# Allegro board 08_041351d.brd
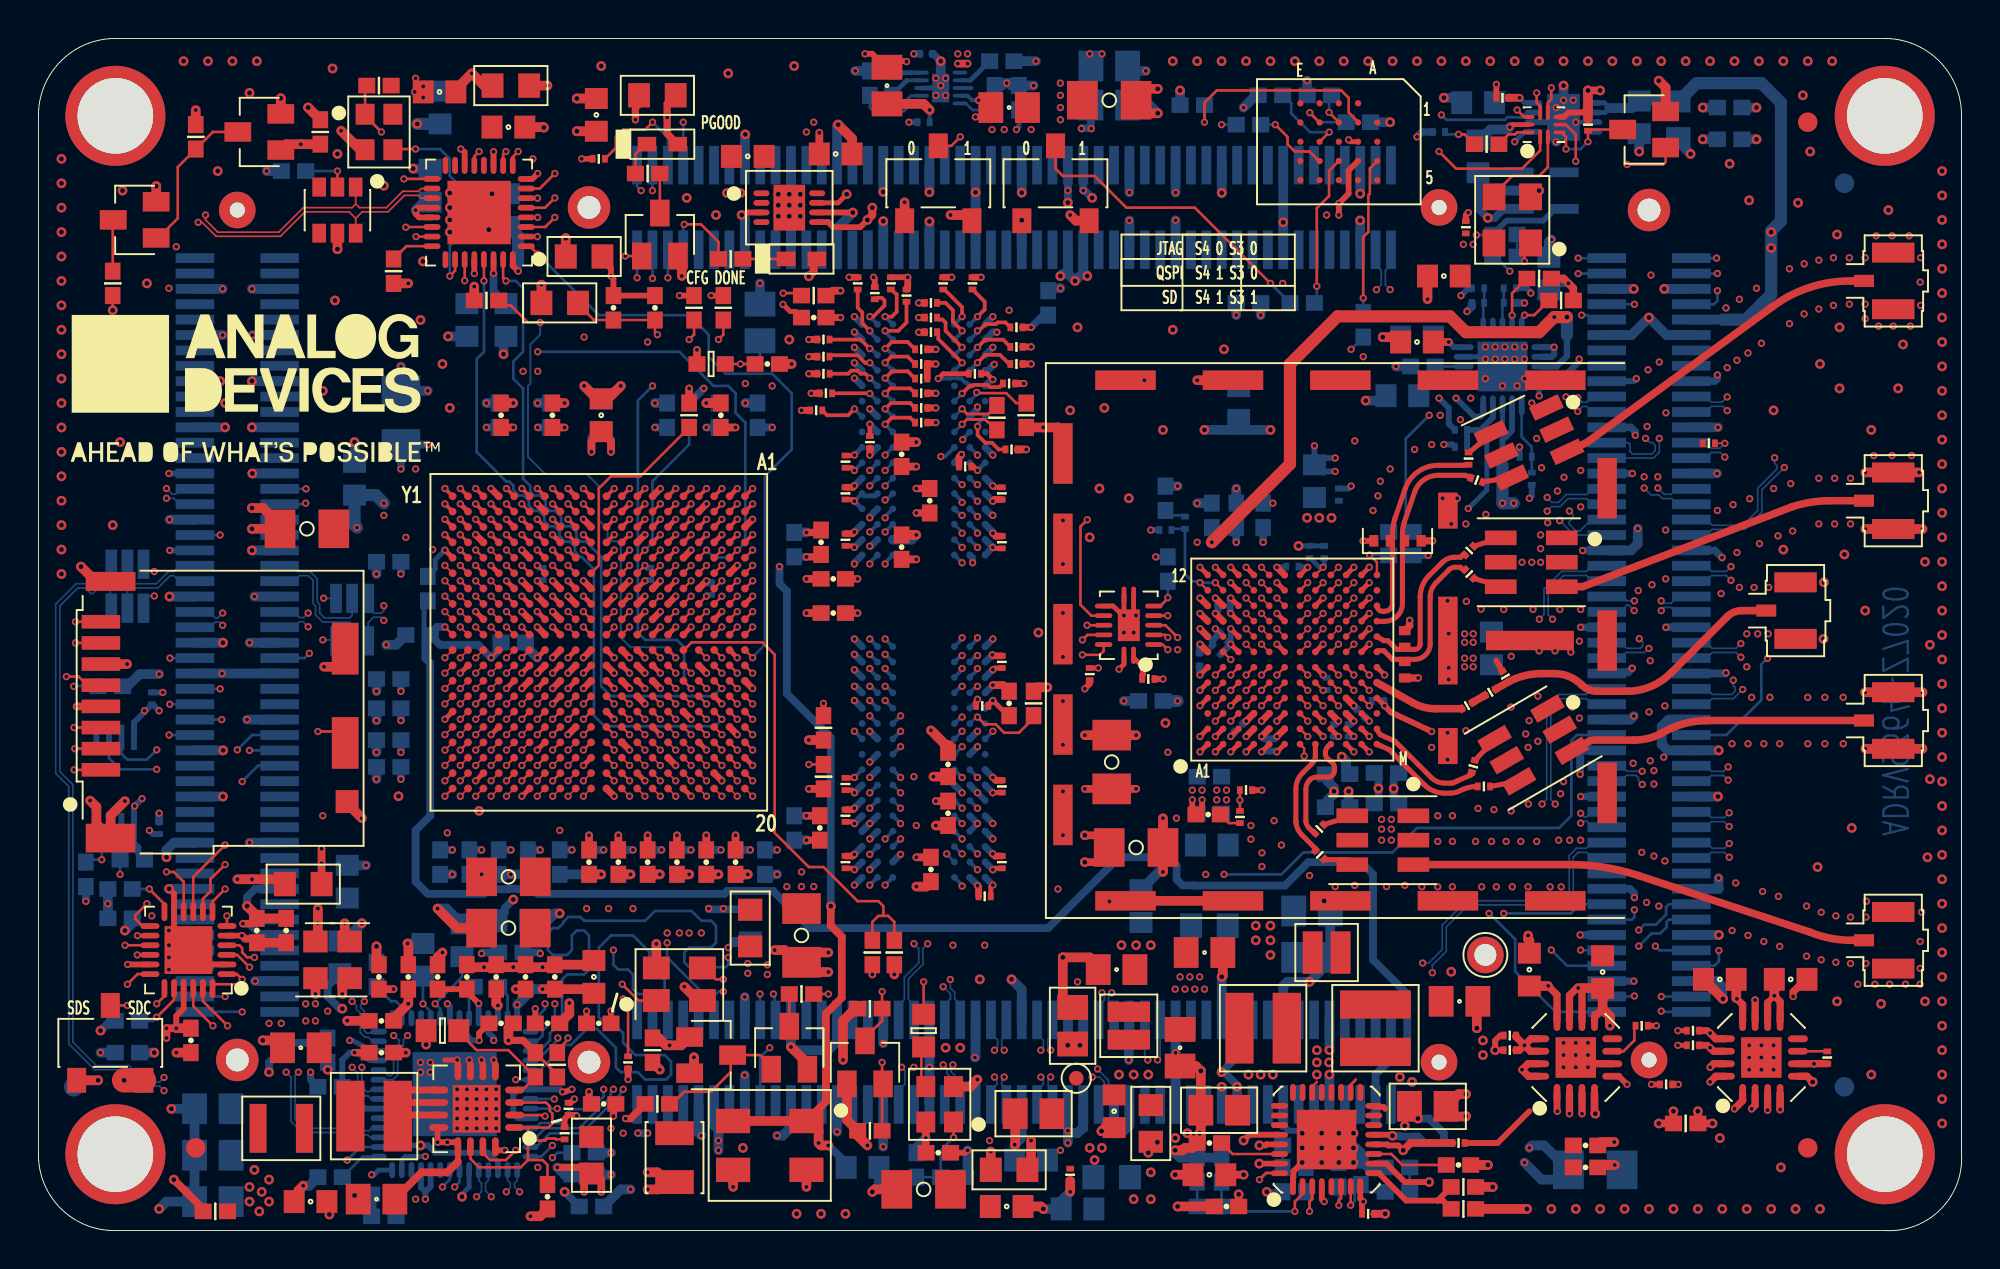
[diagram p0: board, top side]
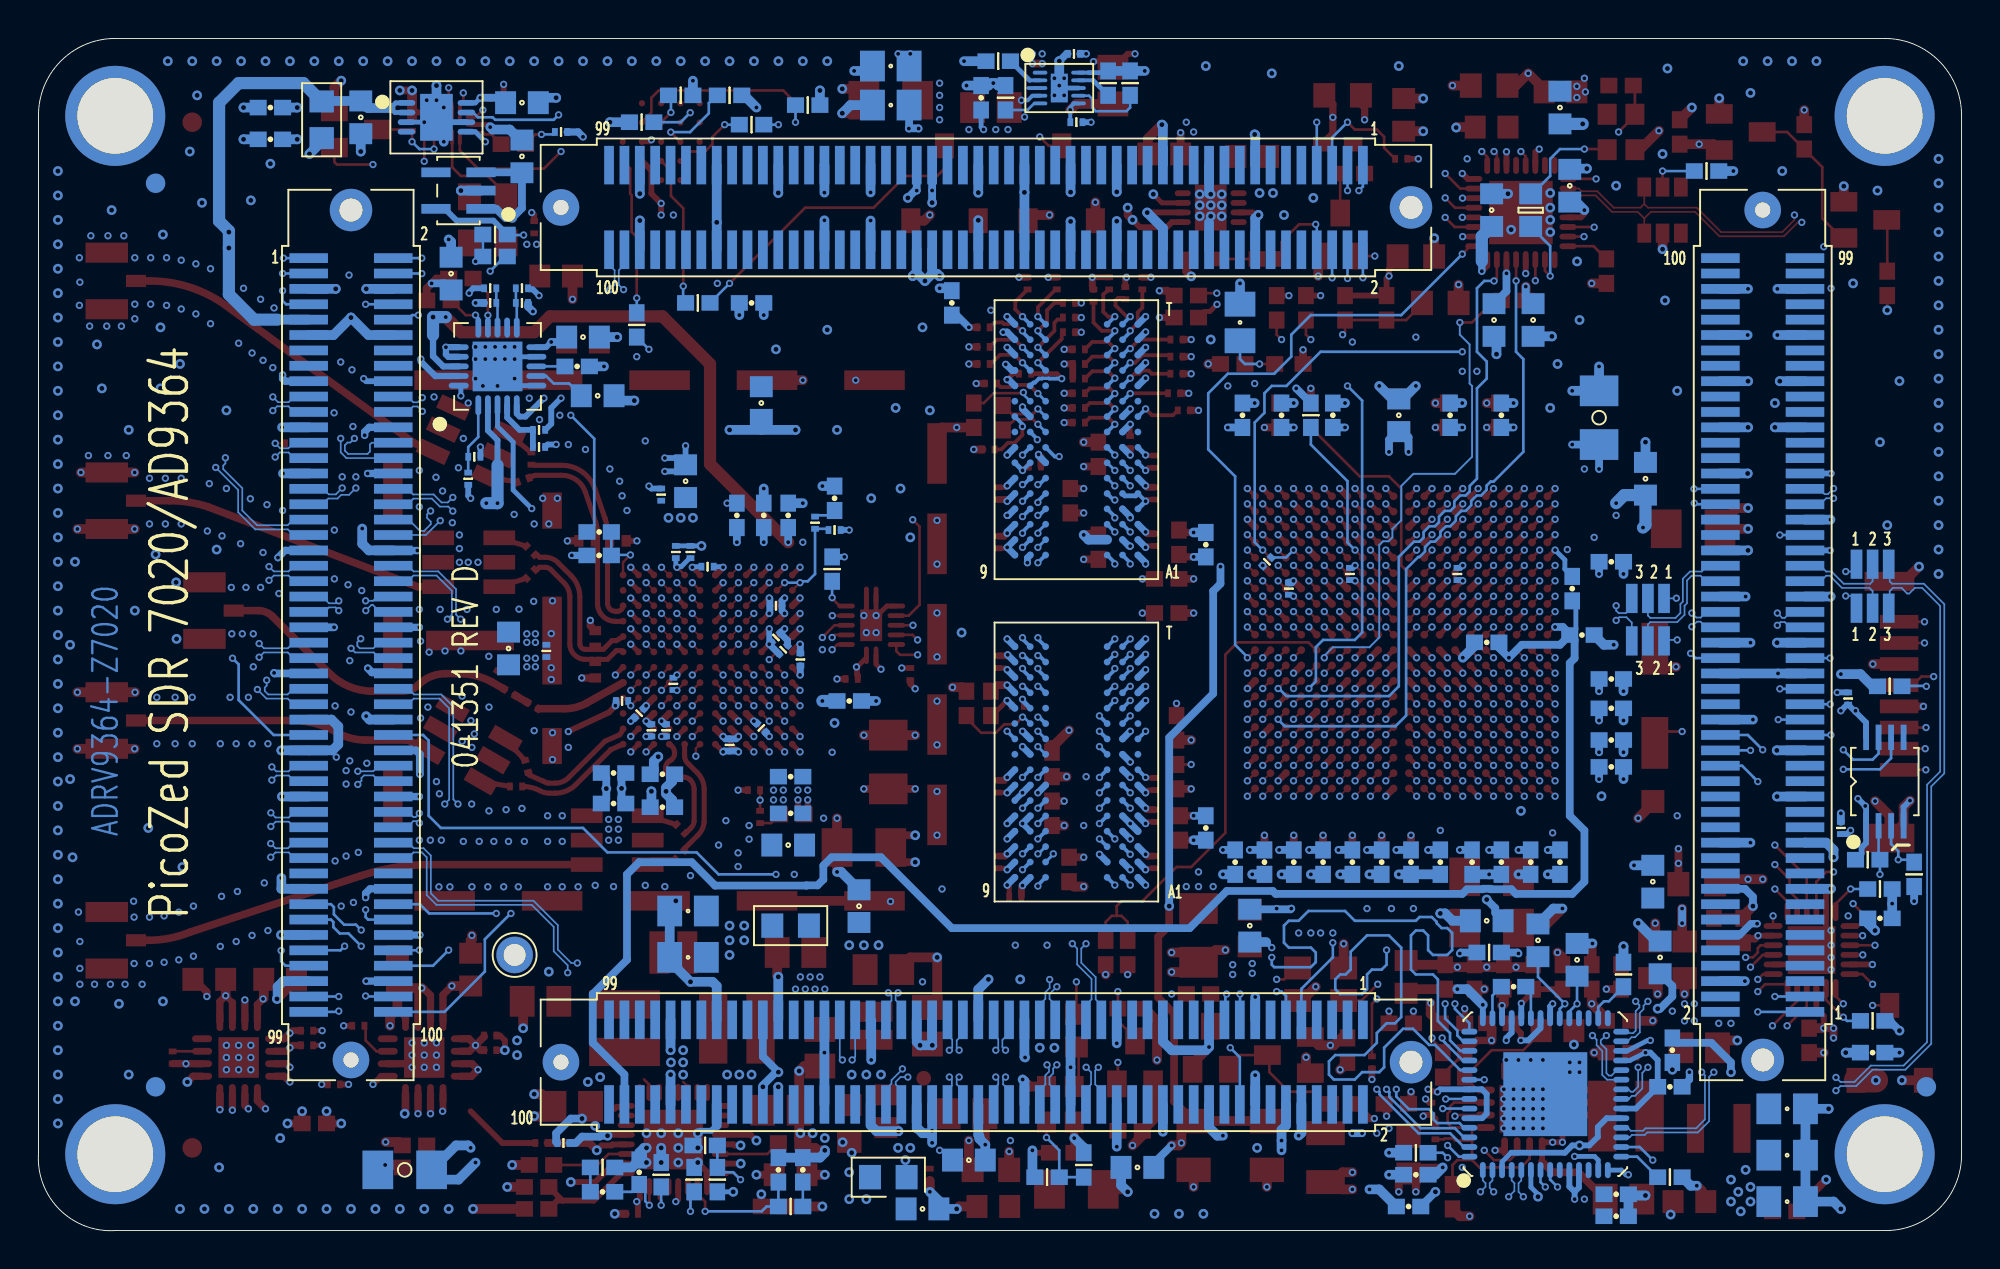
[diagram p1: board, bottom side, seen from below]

Outline 99.99 x 61.99 mm; copper layers: TOP, L2_GROUND, L3_SIGNAL, L4_SIGNAL, L5_GROUND, L6_SIGNAL, L7_SIGNAL, L8_GROUND, L9_POWER, L10_POWER, L11_GROUND, L12_SIGNAL, L13_SIGNAL, L14_GROUND, L15_SIGNAL, L16_SIGNAL, L17_GROUND, BOTTOM. Coordinates in mm from the lower left corner of the outline.
Outline path: 0,58 arc(1.17,60.82) 4,61.99 96,61.99 arc(98.83,60.83) 99.99,58 99.99,4 arc(98.9,1.09) 96,0 4,0 arc(1.15,1.15) 0,4 0,58

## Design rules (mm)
constraint set DEFAULT: min track width 0.14
net group DP1: nets UNNAMED_13_CN100PODDEVEN_I16_N4 UNNAMED_13_CN100PODDEVEN_I16_N5
net group DP2: nets UNNAMED_13_CN100PODDEVEN_I17_N4 UNNAMED_13_CN100PODDEVEN_I17_N5
net group DX_0: nets DX_0_N DX_0_P
net group ETH_MD1: nets ETH_MD1_N ETH_MD1_P
net group ETH_MD2: nets ETH_MD2_N ETH_MD2_P
net group ETH_MD3: nets ETH_MD3_N ETH_MD3_P
net group ETH_MD4: nets ETH_MD4_N ETH_MD4_P
net group IO_L01_33_RX_D0: nets IO_L01_35_RX_D0_N IO_L01_35_RX_D0_P
net group IO_L01_34_JX4: nets IO_L01_34_JX4_N IO_L01_34_JX4_P
net group IO_L02_33_RX_D1: nets IO_L02_35_RX_D1_N IO_L02_35_RX_D1_P
net group IO_L02_34_JX4: nets IO_L02_34_JX4_N IO_L02_34_JX4_P
net group IO_L03_33_RX_D2: nets IO_L03_35_RX_D2_N IO_L03_35_RX_D2_P
net group IO_L03_34_JX4: nets IO_L03_34_JX4_N IO_L03_34_JX4_P
net group IO_L04_33_RX_D3: nets IO_L04_35_RX_D3_N IO_L04_35_RX_D3_P
net group IO_L04_34_JX4: nets IO_L04_34_JX4_N IO_L04_34_JX4_P
net group IO_L05_33_RX_D4: nets IO_L05_35_RX_D4_N IO_L05_35_RX_D4_P
net group IO_L05_34_JX4: nets IO_L05_34_JX4_N IO_L05_34_JX4_P
net group IO_L06_33_RX_D5: nets IO_L06_35_RX_D5_N IO_L06_35_RX_D5_P
net group IO_L06_34_JX4: nets IO_L06_34_JX4_N IO_L06_34_JX4_P
net group IO_L07_33_RX_FRAME: nets IO_L07_35_RX_FRAME_N IO_L07_35_RX_FRAME_P
net group IO_L07_34_JX4: nets IO_L07_34_JX4_N IO_L07_34_JX4_P
net group IO_L08_33_FB_CLK: nets IO_L08_35_FB_CLK_N IO_L08_35_FB_CLK_P
net group IO_L08_34_JX4: nets IO_L08_34_JX4_N IO_L08_34_JX4_P
net group IO_L09_33_TX_FRAME: nets IO_L09_35_TX_FRAME_N IO_L09_35_TX_FRAME_P
net group IO_L09_34_JX4: nets IO_L09_34_JX4_N IO_L09_34_JX4_P
net group IO_L10_34_JX4: nets IO_L10_34_JX4_N IO_L10_34_JX4_P
net group IO_L11_SRCC_13_JX2: nets IO_L11_SRCC_13_JX2_N IO_L11_SRCC_13_JX2_P
net group IO_L11_SRCC_34_JX4: nets IO_L11_SRCC_34_JX4_N IO_L11_SRCC_34_JX4_P
net group IO_L12_MRCC_13_JX2: nets IO_L12_MRCC_13_JX2_N IO_L12_MRCC_13_JX2_P
net group IO_L12_MRCC_34_JX4: nets IO_L12_MRCC_34_JX4_N IO_L12_MRCC_34_JX4_P
net group IO_L13_33_TX_D0: nets IO_L13_35_TX_D0_N IO_L13_35_TX_D0_P
net group IO_L13_MRCC_13_JX2: nets IO_L13_MRCC_13_JX2_N IO_L13_MRCC_13_JX2_P
net group IO_L13_MRCC_34_JX4: nets IO_L13_MRCC_34_JX4_N IO_L13_MRCC_34_JX4_P
net group IO_L14_33_TX_D1: nets IO_L14_35_TX_D1_N IO_L14_35_TX_D1_P
net group IO_L14_SRCC_13_JX2: nets IO_L14_SRCC_13_JX2_N IO_L14_SRCC_13_JX2_P
net group IO_L14_SRCC_34_JX4: nets IO_L14_SRCC_34_JX4_N IO_L14_SRCC_34_JX4_P
net group IO_L15_13_JX2: nets IO_L15_13_JX2_N IO_L15_13_JX2_P
net group IO_L15_33_TX_D2: nets IO_L15_35_TX_D2_N IO_L15_35_TX_D2_P
net group IO_L15_34_JX4: nets IO_L15_34_JX4_N IO_L15_34_JX4_P
net group IO_L16_13_JX2: nets IO_L16_13_JX2_N IO_L16_13_JX2_P
net group IO_L16_33_TX_D3: nets IO_L16_35_TX_D3_N IO_L16_35_TX_D3_P
net group IO_L16_34_JX4: nets IO_L16_34_JX4_N IO_L16_34_JX4_P
net group IO_L17_13_JX2: nets IO_L17_13_JX2_N IO_L17_13_JX2_P
net group IO_L17_33_TX_D4: nets IO_L17_35_TX_D4_N IO_L17_35_TX_D4_P
net group IO_L17_34_JX4: nets IO_L17_34_JX4_N IO_L17_34_JX4_P
net group IO_L18_13_JX2: nets IO_L18_13_JX2_N IO_L18_13_JX2_P
net group IO_L18_33_TX_D5: nets IO_L18_35_TX_D5_N IO_L18_35_TX_D5_P
net group IO_L18_34_JX4: nets IO_L18_34_JX4_N IO_L18_34_JX4_P
net group IO_L19_13_JX2: nets IO_L19_13_JX2_N IO_L19_13_JX2_P
net group IO_L19_34_JX4: nets IO_L19_34_JX4_N IO_L19_34_JX4_P
net group IO_L20_13_JX2: nets IO_L20_13_JX2_N IO_L20_13_JX2_P
net group IO_L20_34_JX4: nets IO_L20_34_JX4_N IO_L20_34_JX4_P
net group IO_L21_13_JX2: nets IO_L21_13_JX2_N IO_L21_13_JX2_P
net group IO_L21_34_JX4: nets IO_L21_34_JX4_N IO_L21_34_JX4_P
net group IO_L22_34_JX4: nets IO_L22_34_JX4_N IO_L22_34_JX4_P
net group RXB: nets RXB_N RXB_P
net group RXB1: nets UNNAMED_8_CAP_I416_N1 UNNAMED_8_CAP_I417_N1
net group S_IN: nets S_IN_N S_IN_P
net group S_OUT: nets S_OUT_N S_OUT_P
net group TXB: nets TXB_N TXB_P
net group TXB1: nets UNNAMED_8_CAP_I409_N2 UNNAMED_8_CAP_I410_N2
net group USB_OTG: nets USB_OTG_N USB_OTG_P
net group CARRIER_RESET: nets CARRIER_RESET SDIO_CMDB1 VCC-3P3V-IO
net group DDR3_DQS0: nets DDR3_DQS0_N
net group DDR3_DQS1: nets DDR3_DQS1_N
net group DDR3_DQS2: nets DDR3_DQS2_N
net group DDR3_DQS3: nets DDR3_DQS3_N
net group DDR3_LANE0: nets DDR3_DM0 DDR3_DQ0 DDR3_DQ1 DDR3_DQ2 DDR3_DQ3 DDR3_DQ4 DDR3_DQ5 DDR3_DQ6 DDR3_DQ7 DDR3_DQS0_P
net group DDR3_LANE1: nets DDR3_DM1 DDR3_DQ8 DDR3_DQ9 DDR3_DQ10 DDR3_DQ11 DDR3_DQ12 DDR3_DQ13 DDR3_DQ14 DDR3_DQ15 DDR3_DQS1_P
net group DDR3_LANE2: nets DDR3_DM2 DDR3_DQ16 DDR3_DQ17 DDR3_DQ18 DDR3_DQ19 DDR3_DQ20 DDR3_DQ21 DDR3_DQ22 DDR3_DQ23 DDR3_DQS2_P
net group DDR3_LANE3: nets DDR3_DM3 DDR3_DQ24 DDR3_DQ25 DDR3_DQ26 DDR3_DQ27 DDR3_DQ28 DDR3_DQ29 DDR3_DQ30 DDR3_DQ31 DDR3_DQS3_P
net group PS_MIO_A: nets PS_MIO07_500_USB_RESET_B PS_MIO09_500_USB_CLK_PD PS_MIO28_501_USB0_D4 PS_MIO29_501_USB0_DIR PS_MIO30_501_USB0_STP PS_MIO31_501_USB0_NXT PS_MIO32_501_USB0_D0 PS_MIO33_501_USB0_D1 PS_MIO34_501_USB0_D2 PS_MIO35_501_USB0_D3 PS_MIO36_501_USB0_CLK PS_MIO37_501_USB0_D5 PS_MIO38_501_USB0_D6 PS_MIO39_501_USB0_D7
net group PS_MIO_E: nets PS_MIO08_500_ETH0_RESETN PS_MIO16_501_ETH0_TX_CLK PS_MIO17_501_ETH0_TX_D0 PS_MIO18_501_ETH0_TX_D1 PS_MIO19_501_ETH0_TX_D2 PS_MIO20_501_ETH0_TX_D3 PS_MIO21_501_ETH0_TX_CTL PS_MIO22_501_ETH0_RX_CLK PS_MIO23_501_ETH0_RX_D0 PS_MIO24_501_ETH0_RX_D1 PS_MIO25_501_ETH0_RX_D2 PS_MIO26_501_ETH0_RX_D3 PS_MIO27_501_ETH0_RX_CTL PS_MIO52_501_ETH0_MDC PS_MIO53_501_ETH0_MDIO
net group TXA_N: nets TXA_N
net group TXA_P: nets TXA_P

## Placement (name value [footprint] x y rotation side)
C1  100uF  [C1206H71]  24.44 15.73 180 top
C2  100uF  [C1206H71]  55.81 24.37 90 top
C3  4.7uF  [C0402]  22.4 19.16 270 bottom
C4  4.7uF  [C0402]  25.45 19.16 270 bottom
C5  4.7uF  [C0603]  73.08 49.64 180 top
C6  0.001uF  [C0201]  74.28 27.3 210 top
C7  0.47uF  [C0402]  23.93 19.16 270 bottom
C8  18PF  [C0201]  74.61 24.14 255 top
C9  18PF  [C0201]  75.16 23.1 180 top
C10  0.47uF  [C0402]  41.33 33.89 0 top
C11  0.47uF  [C0402]  32.69 42.4 90 bottom
C12  1uF  [C0402]  60.82 21.63 0 top
C13  0.001uF  [C0201]  62.79 22.9 180 top
C14  0.001uF  [C0201]  73.59 30.14 270 bottom
C15  0.47uF  [C0402]  20.88 19.16 270 bottom
C16  0.47uF  [C0402]  27.1 19.16 270 bottom
C17  0.47uF  [C0402]  26.6 42.4 90 bottom
C18  0.47uF  [C0402]  18.21 24.11 180 bottom
C19  0.47uF  [C0402]  36.25 19.16 270 top
C20  0.47uF  [C0402]  23.93 42.4 90 bottom
C21  10uF  [C0603]  75.55 30.27 90 bottom
C22  0.47uF  [C0402]  18.21 25.51 180 bottom
C23  0.47uF  [C0402]  28.63 19.16 270 top
C24  22uF  [C0603]  62.41 43.03 90 bottom
C25  18PF  [C0201]  74.4 35.36 45 top
C26  18PF  [C0201]  74.4 34.14 315 top
C27  100uF  [C1206H71]  18.85 42.27 90 bottom
C28  100uF  [C1206H71]  39.68 15.35 90 top
C29  100uF  [C1206H71]  13.96 36.49 180 top
C30  22uF  [C0603]  29.26 42.4 90 bottom
C31  4.7uF  [C0402]  33.2 19.16 270 bottom
C32  0.1UF  [C0603]  24.31 47.35 270 bottom
C33  4.7uF  [C0402]  30.15 19.16 270 bottom
C34  0.1UF  [C0603]  42.85 3.28 0 bottom
C35  0.47uF  [C0402]  31.68 19.16 270 bottom
C36  1uF  [C0603]  41.45 55.99 0 top
C37  10uF  [C0805H53]  61.39 6.26 180 top
C38  10uF  [C0603]  36.88 55.86 0 top
C39  0.1uF  [C0402]  46.79 4.05 0 top
C40  0.1uF  [C0402]  62.92 48.24 0 bottom
C41  0.1uF  [C0402]  7.93 9.89 270 top
C42  0.1uF  [C0402]  4.24 16.24 0 bottom
C43  0.01uF  [C0201]  46.15 61.2 180 bottom
C44  0.47uF  [C0402]  31.68 19.16 270 top
C45  10uF  [C0805H53]  72.24 6.46 0 top
C46  0.47uF  [C0402]  18.21 28.68 180 bottom
C47  0.47uF  [C0402]  33.2 19.16 270 top
C48  0.47uF  [C0402]  24.69 30.59 0 bottom
C49  4.7uF  [C0402]  17.71 13.19 90 top
C50  4.7uF  [C0402]  26.47 10.78 0 top
C51  0.47uF  [C0402]  30.15 19.16 270 top
C52  4.7uF  [C0402]  36.25 19.16 270 bottom
C53  0.47uF  [C0402]  35.49 42.4 90 top
C54  0.1uF  [C0402]  11.36 15.6 90 top
C55  0.1uF  [C0402]  12.88 15.6 90 top
C56  100uF  [C1206H71]  57.08 19.92 0 top
C57  0.1uF  [C0402]  4.62 9.25 0 bottom
C58  1uF  [C0603]  28.88 13.19 90 top
C59  27PF  [C0603]  19.99 14.08 90 bottom
C60  27PF  [C0603]  22.02 15.09 90 bottom
C61  0.1UF  [C0402]  26.47 1.76 270 top
C62  0  [R0402]  75.3 56.5 0 top
C63  4.7uF  [C0402]  26.85 13.19 90 top
C64  22uF  [C0805H60]  59.36 9.51 270 top
C65  22uF  [C0805H60]  73.89 11.92 0 top
C66  47uF  [C0805H60]  17.58 1.63 180 top
C67  150pF  [C0402]  61.52 3.16 90 bottom
C68  180PF  [C0402]  68.76 3.03 90 bottom
C69  5.6NF  [C0402H22]  60.25 3.16 90 bottom
C70  4.7uF  [C0402]  39.3 20.94 270 bottom
C71  22uF  [C0603]  29.26 42.4 90 top
C72  0.47uF  [C0402]  40.63 20.94 270 top
C73  0.1uF  [C0402]  23.8 13.19 90 top
C74  4.7uF  [C0402]  17.96 1.89 180 bottom
C75  0.1uF  [C0402]  28.75 1.25 0 bottom
C76  0.01uF  [C0201]  26.21 34.14 270 bottom
C77  0.01uF  [C0201]  31.8 34.14 270 bottom
C78  1uF  [C0603]  14.15 1.51 180 top
C79  10uF  [C0805H60]  50.47 58.4 180 top
C80  15NF  [C0402H22]  50.98 58.91 270 bottom
C81  0.22UF  [C0805]  44.12 59.54 90 top
C82  10uF  [C0805H60]  55.68 58.53 0 bottom
C83  10uF  [C0805H60]  55.68 60.56 0 bottom
C84  0.01uF  [C0201]  46.03 57.64 180 bottom
C85  18PF  [C0201]  66.6 20.89 225 top
C86  4.7uF  [C0402]  47.3 21.7 270 top
C87  4.7uF  [C0402]  50.47 27.41 270 top
C88  0.47uF  [C0402]  46.41 18.78 270 top
C89  0.47uF  [C0402]  47.3 24.24 270 top
C90  18PF  [C0201]  66.63 19.54 135 top
C91  0.1uF  [C0201]  49.2 17.38 0 top
C92  0.1uF  [C0201]  50.09 29.57 270 top
C93  0.001uF  [C0201]  67.62 38.27 270 bottom
C94  0.1uF  [C0201]  50.09 23.1 270 top
C95  0.1uF  [C0201]  50.09 19.16 270 top
C96  0.1uF  [C0201]  41.96 21.57 270 top
C97  0.1uF  [C0201]  41.96 19.16 270 top
C98  10uF  [C0603]  66.35 38.97 90 bottom
C99  18PF  [C0201]  74.36 40.15 90 top
C100  100uF  [C1206H71]  55.68 58.78 0 top
C101  4.7uF  [C0402]  52.5 48.24 90 bottom
C102  0.01uF  [C0201]  41.96 39.99 270 top
C103  0.01uF  [C0201]  41.96 23.22 270 top
C104  0.001uF  [C0201]  58.6 36.43 0 bottom
C105  1uF  [C0402]  58.6 38.08 270 bottom
C106  4.7uF  [C0402]  44.88 40.37 90 top
C107  0.47uF  [C0402]  46.34 37.95 90 top
C108  0.47uF  [C0402]  44.88 35.54 90 top
C109  0.1uF  [C0201]  50.09 38.34 90 top
C110  18PF  [C0201]  74.79 39.03 340 top
C111  0.1UF  [C0603]  71.68 46.21 0 top
C112  0.1uF  [C0201]  50.09 35.8 270 top
C113  0.1uF  [C0201]  74.22 52.18 90 top
C114  0.0033uF  [C0402]  70.66 2.01 0 bottom
C115  0.1uF  [C0201]  41.96 35.92 270 top
C116  0.1uF  [C0201]  48.19 39.73 0 top
C117  0.1uF  [C0201]  43.23 41 90 top
C118  0.1uF  [C0201]  41.96 38.34 270 top
C119  47uF  [C0805H60]  13.64 9.51 180 top
C120  4.7uF  [C0402]  40.31 47.48 180 top
C121  4.7uF  [C0402]  35.36 42.4 90 bottom
C122  0.01uF  [C0201]  48.69 44.56 180 top
C123  0.01uF  [C0201]  49.07 27.29 180 top
C124  10uF  [C0603]  71.68 46.46 180 bottom
C125  0.47uF  [C0402]  37.39 42.4 90 bottom
C126  0.1UF  [C0603]  20.88 58.4 90 bottom
C127  56000PF  [C0402]  15.04 9.38 90 bottom
C128  47uF  [C0805H60]  9.07 6.33 180 bottom
C129  47uF  [C0805H60]  60.63 14.46 0 top
C130  47uF  [C0805H60]  9.07 3.92 180 bottom
C131  47uF  [C0805H60]  9.07 1.51 180 bottom
C132  47uF  [C0805H60]  66.22 16.62 0 bottom
C133  4.7uF  [C0402]  71.99 44.94 180 bottom
C134  10uF  [C0603]  78.54 49.77 90 bottom
C135  47uF  [C0805H60]  56.06 13.57 180 top
C136  47uF  [C0805H60]  66.22 14.21 0 bottom
C137  10uF  [C0805H53]  53.77 10.65 90 top
C138  100uF  [C1206H71]  46.03 2.14 180 top
C139  10uF  [C0805H53]  51.74 6.08 180 top
C140  4.7uF  [C0402]  34.72 19.16 270 bottom
C141  4.7uF  [C0402]  34.72 19.16 270 top
C142  0.047UF  [C0402]  60.89 4.55 0 top
C143  0.47uF  [C0402]  28.63 19.16 270 bottom
C144  0.047UF  [C0402]  73.84 3.41 180 top
C145  22uF  [C0603]  16.44 39.1 270 bottom
C146  1uF  [C0402]  61.77 1.25 180 top
C147  10uF  [C0603]  57.33 16.87 90 bottom
C148  10uF  [C0402]  80.44 4.43 0 top
C149  10uF  [C0402]  80.44 3.28 0 top
C150  0.047uF  [C0603]  60.89 2.9 180 top
C151  100uF  [C1206H71]  24.44 18.4 180 top
C152  4.7uF  [C0603]  74.86 55.86 90 bottom
C158  10uF  [C0603]  70.92 43.42 180 bottom
C159  4.7uF  [C0402]  40.69 35.8 90 top
C162  0.47uF  [C0402]  39.3 35.67 90 bottom
C163  0.47uF  [C0402]  41.33 32.11 0 top
C165  18PF  [C0402]  70.84 35.11 0 bottom
C167  4.7uF  [C0402]  18.21 27.16 180 bottom
C169  4.7uF  [C0402]  20.25 33.38 90 bottom
C170  0.47uF  [C0402]  19.74 30.97 180 bottom
C171  0.47uF  [C0402]  18.21 34.78 180 bottom
C173  100uF  [C1206H71]  80.95 3.16 0 bottom
C174  4.7uF  [C0402]  37.77 19.16 270 bottom
C175  4.7uF  [C0402]  26.72 42.4 90 top
C178  0.47uF  [C0402]  37.9 45.07 0 top
C179  0.47uF  [C0402]  24.06 42.4 90 top
C181  1uF  [C0603]  24.44 53.07 90 bottom
C182  1uF  [C0603]  22.28 47.35 270 bottom
C183  1uF  [C0603]  24.44 57.39 0 top
C184  1uF  [C0603]  20.37 54.34 90 bottom
C188  0.1uF  [C0201]  76.13 58.91 0 top
C189  0.47uF  [C0402]  29.9 47.99 90 top
C190  0.1uF  [C0402]  32.06 47.99 90 top
C191  10uF  [C0603]  55.93 6.2 270 top
C193  10uF  [C0603]  50.34 1.25 0 top
C194  10uF  [C0603]  54.03 1.12 180 bottom
C195  10uF  [C0603]  37.01 15.86 270 bottom
C196  10uF  [C0603]  20.85 59.21 180 top
C197  10uF  [C0603]  29.01 58.02 270 top
C198  10uF  [C0603]  16.05 18.14 90 bottom
C199  1uF  [C0603]  74.86 58.66 180 bottom
C200  10uF  [C0603]  83.24 57.89 270 bottom
C201  0.1uF  [C0402]  20.75 13.19 90 top
C203  0.1uF  [C0402]  17.83 10.9 180 top
C206  0.1uF  [C0402]  17.96 0.74 180 bottom
C208  0.1uF  [C0402]  17.83 9.25 0 top
C210  10uF  [C0603]  24.69 16.11 0 bottom
C211  0.1uF  [C0402]  19.23 13.19 90 top
C212  0.1uF  [C0402]  28.37 2.9 0 bottom
C214  0.1uF  [C0402]  15.17 7.47 180 bottom
C216  18PF  [C0402]  70.84 36.33 180 bottom
C217  0.1uF  [C0402]  25.33 13.19 90 top
C218  4.7uF  [C0402]  22.28 13.19 90 top
C219  1uF  [C0603]  15.67 14.21 90 bottom
C224  0.1uF  [C0402]  29.39 6.59 0 top
C225  0.1uF  [C0402]  29.14 10.78 0 top
C226  0.1uF  [C0402]  24.06 10.78 0 top
C242  0.1uF  [C0402]  23.29 12.68 180 bottom
C243  0.1uF  [C0201]  6.28 20.94 90 bottom
C244  0.1uF  [C0201]  5.89 27.67 270 bottom
C245  0.1uF  [C0201]  57.71 28.68 0 top
C246  0.1uF  [C0201]  54.66 28.94 270 top
C251  47uF  [C0805H60]  37.52 47.23 90 bottom
C311  0.01uF  [C0201]  83.36 10.65 0 top
C312  10uF  [C0603]  81.33 13.44 90 top
C313  10uF  [C0603]  77.52 13.57 90 top
C314  0.1uF  [C0201]  76.51 10.14 180 top
C315  0.1uF  [C0201]  76.51 9.38 180 top
C319  0.1uF  [C0201]  61.65 30.84 315 bottom
C320  1uF  [C0402]  70.09 23.79 0 bottom
C321  0.01uF  [C0201]  61.65 32.49 0 bottom
C322  0.01uF  [C0201]  64.06 25.25 270 bottom
C323  1uF  [C0402]  70.09 22.21 0 bottom
C324  1uF  [C0402]  67.55 23.73 180 bottom
C325  0.01uF  [C0201]  60.38 29.7 270 bottom
C326  0.01uF  [C0201]  67.36 26.02 270 bottom
C327  1uF  [C0402]  61.01 37.19 90 bottom
C328  1uF  [C0402]  67.55 22.02 180 bottom
C329  0.01uF  [C0201]  68.12 26.02 270 bottom
C330  0.01uF  [C0201]  65.2 34.53 0 bottom
C331  1uF  [C0402]  57.84 27.54 180 bottom
C332  1uF  [C0402]  62.28 37.19 90 bottom
C333  0.01uF  [C0201]  68.76 26.91 315 bottom
C334  0.01uF  [C0201]  62.41 26.14 225 bottom
C335  1uF  [C0402]  63.68 37.19 90 bottom
C340  0.01uF  [C0201]  93.02 9 270 top
C341  10uF  [C0603]  91.11 13.06 0 top
C342  10uF  [C0603]  87.43 13.06 180 top
C343  0.1uF  [C0201]  86.03 10.4 180 top
C344  0.1uF  [C0201]  86.03 9.63 180 top
C354  1uF  [C0402]  60.89 23.6 180 bottom
C355  0.01uF  [C0201]  66.09 35.29 90 bottom
C356  0.01uF  [C0201]  66.85 35.29 90 bottom
C357  1uF  [C0402]  60.89 21.7 180 bottom
C358  1uF  [C0402]  87.94 56.75 0 bottom
C360  0.01uF  [C0201]  61.27 30.21 315 bottom
C361  1uF  [C0402]  87.94 58.4 0 bottom
C363  10uF  [C0603]  61.01 20.05 180 bottom
C364  0.1uF  [C0201]  53.65 2.9 270 top
C365  10uF  [C0603]  51.61 3.66 180 bottom
D3  QTLP600C4TR  [LED0603]  32.44 56.5 0 top
D4  QTLP600C4TR  [LED0603]  39.68 50.53 0 top
E1  220OHM  [L0805]  27.1 48.24 0 top
E2  100OHM  [L0805]  50.47 3.16 180 top
E3  100OHM  [L0805]  60.89 15.86 180 bottom
E4  100OHM  [L0805]  57.84 5.57 90 top
E5  100OHM  [L0805]  55.81 2.78 180 bottom
E6  100OHM  [L0805]  37.01 15.73 90 top
E7  100OHM  [L0805]  24.56 59.54 180 top
E8  100OHM  [L0805]  32.18 59.04 180 top
E9  100OHM  [L0805]  14.4 14.08 90 top
E10  75OHM  [L0402]  85.65 5.57 180 top
E11  100OHM  [L0805]  85.27 57.77 270 bottom
E12  220OHM  [L0805]  28.37 50.65 0 top
E14  100OHM  [L0805]  28.75 3.92 270 top
E15  100OHM  [L0805]  13.77 18.02 0 top
E16  100OHM  [L0805]  16.18 14.08 270 top
J3  DM3CS-SF  [CNHIROSEDM3CS-SF]  9.45 27.16 0 top
JP1  3PIN_SOLDER_JUMPER  [JPRSLD03]  4.62 32.37 180 bottom
JP2  3PIN_SOLDER_JUMPER  [JPRSLD03]  4.62 34.65 180 bottom
JP3  3PIN_SOLDER_JUMPER  [JPRSLD03]  16.31 30.66 0 bottom
JP4  3PIN_SOLDER_JUMPER  [JPRSLD03]  16.31 32.87 0 bottom
JX1  61082-101400LF  [CNFCI61082-101400]  50.73 53.21 0 bottom
JX2  61082-101400LF  [CNFCI61082-101400]  50.73 8.76 0 bottom
JX3  61082-101400LF  [CNFCI61082-101400]  10.34 30.97 90 bottom
JX4  61082-101400LF  [CNFCI61082-101400]  83.75 30.97 270 bottom
L1  330NH  [L0402#2]  69.86 35.87 0 top
L2  330NH  [L0402#2]  71.47 35.87 180 top
L3  1.5uH  [LSMSQ157H83]  63.68 10.52 180 top
L4  1.5uH  [LSMSQ157H83]  69.52 10.52 90 top
L5  1uH  [LSMSQ157H83]  17.45 5.95 180 top
L6  150NH  [L1008_A]  12.63 5.32 180 top
L7  180NH  [LSMSQ79H41]  66.98 14.46 180 top
L8  330NH  [L0402#2]  71.05 30.77 270 top
L9  330NH  [L0402#2]  71.05 29.17 90 top
L10  180NH  [LSMSQ79H41]  56.69 10.65 90 top
L12  600OHMS  [L0603]  34.98 45.07 0 top
L302  0.47UH  [L1210H67]  33.07 3.79 270 top
M1  LT15CCC2243A  [MLT15CCC2243A]  67.42 30.68 180 top
NOREF  -  []  99.19 60.41 0 top
NOREF#2  -  []  99.99 4 0 top
NOREF#3  -  []  27.05 168.46 0 top
NOREF#4  -  []  4 3.97 90 top
NOREF#5  -  [unnamed#2]  8.18 4.3 0 top
NOREF#6  -  []  96 0 90 top
NOREF#7  -  []  -76.66 -229 0 top
NOREF#8  -  []  4 3.97 90 top
NOREF#9  -  [unnamed#2]  96 3.97 0 top
NOREF#10  -  []  53.14 82.28 0 top
NOREF#11  -  [unnamed#2]  96 57.97 0 top
NOREF#12  -  []  4 3.97 0 top
NOREF#13  -  []  -89.23 -241.57 0 top
NOREF#14  -  []  -76.53 -228.87 0 top
NOREF#15  -  []  11.29 43.8 0 top
NOREF#16  -  []  4 3.97 0 top
NOREF#17  -  []  4 3.97 90 top
NOREF#18  -  []  4 0 0 top
NOREF#19  -  []  157 -42.54 0 top
NOREF#20  -  []  0 58 0 top
NOREF#21  -  []  226.11 149.71 0 top
NOREF#22  -  []  4 61.99 0 top
NOREF#23  -  []  0 4 0 top
NOREF#24  -  [unnamed#2]  92 4.3 0 top
NOREF#25  -  []  4 3.97 0 top
NOREF#26  -  [unnamed#2]  92 57.64 0 top
NOREF#27  -  []  4 3.97 0 top
NOREF#28  -  [unnamed#2]  4 57.97 0 top
NOREF#29  -  [unnamed#2]  4 3.97 0 top
NOREF#30  -  [unnamed#2]  93.91 7.47 180 bottom
NOREF#31  -  [unnamed#2]  1.83 7.47 180 bottom
NOREF#32  -  [unnamed#2]  93.91 54.46 180 bottom
Q1  BSS138TA  [SOT23]  34.98 9.13 270 top
Q2  BSS138TA  [SOT23]  11.48 57.13 90 top
Q3  BSS138TA  [SOT23]  39.04 9.51 0 top
Q4  BSS138TA  [SOT23]  5.01 52.56 90 top
Q5  BSS138LT1G  [SOT23]  42.98 8.74 0 top
Q6  BSS138LT1G  [SOT23]  83.49 57.26 90 top
Q14  BSS138LT1G  [SOT23]  32.31 51.8 0 top
R1  10  [R0201]  75.49 27.99 210 top
R2  1  [R0201]  62.47 21.51 270 top
R3  0  [R0402]  24.56 14.46 0 bottom
R4  4.99K  [R0402]  4.24 17.76 0 bottom
R5  49.9  [R0201]  72.82 57.13 180 bottom
R6  0  [R0402]  50.09 60.81 180 bottom
R7  10K  [R0402]  43.23 5.19 0 top
R8  10K  [R0402]  43.23 11.54 0 top
R9  0  [R0402]  23.29 48.37 0 top
R10  27.4K  [R0402]  65.9 2.65 270 bottom
R11  4.99K  [R0402]  28.37 4.05 180 bottom
R12  0  [R0402]  15.17 2.78 0 bottom
R13  1K  [R0402]  31.93 9.38 270 top
R14  1K  [R0402]  14.66 57.13 90 top
R15  1K  [R0402]  32.18 6.59 0 top
R16  1K  [R0402]  8.18 56.88 270 top
R17  220  [R0402]  39.68 12.3 0 top
R18  220  [R0402]  3.86 49.26 270 top
R19  0  [R0402]  68.89 47.1 90 bottom
R20  4.75K  [R0402]  67.62 2.9 270 bottom
R22  10K  [R0201]  73.84 4.55 0 top
R23  10  [R0201]  69.14 0.87 180 top
R25  10K  [R0201]  72.7 4.55 0 bottom
R26  10K  [R0402]  40.82 26.14 270 top
R27  10K  [R0402]  17.71 59.54 0 top
R28  240  [R0402]  66.6 59.04 0 bottom
R29  30K  [R0402]  25.83 8.62 270 top
R31  20K  [R0201]  34.98 33.38 270 bottom
R32  20K  [R0201]  36.12 34.78 135 bottom
R33  10K  [R0201]  80.57 57.51 270 top
R34  15K  [R0402]  74.09 1.12 0 top
R35  18.7K  [R0402]  74.09 2.27 0 top
R36  20K  [R0402]  3.74 28.3 180 bottom
R37  10K  [R0402]  40.82 23.6 90 top
R38  44.2K  [R0402]  26.98 8.62 270 top
R39  46.4K  [R0402]  64.7 2.65 90 bottom
R40  10K  [R0402]  45.65 3.41 270 bottom
R41  10K  [R0402]  47.55 2.78 0 bottom
R42  4.7K  [R0402]  78.03 49.51 180 top
R43  10K  [R0201]  30.66 8.74 90 top
R44  4.7K  [R0402]  79.17 48.37 180 top
R45  23.2K  [R0402]  65.33 4.43 0 bottom
R46  10K  [R0402]  60.89 1.25 180 bottom
R47  10K  [R0402]  70.66 3.28 180 bottom
R48  19.6K  [R0603]  21.01 10.4 180 top
R49  1K  [R0402]  9.2 1 0 top
R50  4.99K  [R0402]  17.58 13.32 90 bottom
R53  1K  [R0201]  86.86 40.94 180 top
R54  301  [R0402]  76.25 50.65 0 bottom
R55  1K  [R0402]  76.25 51.8 0 bottom
R56  10K  [R0201]  29.14 55.73 0 top
R57  4.7K  [R0402]  2.47 18.52 90 bottom
R58  4.7K  [R0402]  4.88 19.29 180 bottom
R59  1K  [R0402]  58.73 34.4 90 bottom
R61  4.02K  [R0201]  73.97 41.64 0 bottom
R62  4.02K  [R0201]  73.97 40.75 180 bottom
R63  10K  [R0201]  76.51 48.24 180 bottom
R64  10K  [R0201]  76.51 49 0 bottom
R65  10K  [R0201]  74.86 48.24 0 bottom
R66  10K  [R0201]  74.86 49 180 bottom
R67  4.02K  [R0201]  77.65 39.1 90 bottom
R68  4.02K  [R0201]  77.33 40.24 180 bottom
R101  49.9  [R0201]  76.28 28.81 120 top
R109  4.99K  [R0402]  4.62 10.9 0 bottom
R111  10K  [R0201]  66.98 28.43 270 bottom
R113  130  [R0402]  31.68 54.97 0 top
R114  39  [R0603]  46.03 10.4 90 top
R116  20K  [R0402]  60 58.53 180 bottom
R119  20K  [R0402]  68.63 57.64 0 bottom
R120  20K  [R0402]  64.06 59.04 180 bottom
R121  20K  [R0402]  65.71 48.24 180 bottom
R122  20K  [R0402]  62.92 57.51 180 bottom
R123  1  [R0201]  59.62 36.81 90 bottom
R125  14.3K  [R0201]  69.65 27.54 0 bottom
R133  1K  [R0201]  43.49 48.75 90 top
R134  240  [R0402]  40.31 48.62 0 top
R135  240  [R0402]  33.83 42.4 90 bottom
R136  120  [R0201]  45.9 45.07 0 top
R137  120  [R0201]  46.41 47.48 180 top
R138  120  [R0201]  45.9 45.83 0 top
R139  120  [R0201]  40.82 45.45 180 top
R140  120  [R0201]  50.85 45.96 0 top
R141  120  [R0201]  40.82 46.34 180 top
R142  80.6  [R0402]  49.84 42.27 90 top
R143  120  [R0201]  50.85 46.97 0 top
R144  120  [R0201]  42.6 49.26 90 top
R145  120  [R0201]  48.57 49.26 90 top
R146  120  [R0201]  45.14 48.62 90 top
R147  120  [R0201]  50.47 44.05 0 top
R148  120  [R0201]  46.41 48.24 180 top
R149  120  [R0201]  46.41 46.72 180 top
R150  120  [R0201]  44.32 49.26 90 top
R151  120  [R0201]  47.04 49.26 90 top
R152  120  [R0201]  40.82 44.56 180 top
R153  120  [R0201]  50.85 45.07 0 top
R154  120  [R0201]  45.9 44.3 0 top
R155  120  [R0201]  45.9 43.54 0 top
R156  120  [R0201]  45.9 42.02 0 top
R159  120  [R0201]  45.9 42.78 0 top
R160  120  [R0201]  50.6 40.62 0 top
R161  0  [R0402]  49.71 58.91 270 bottom
R162  120  [R0201]  40.44 42.65 180 top
R163  120  [R0201]  40.95 43.54 180 top
R165  240  [R0402]  51.74 27.41 90 top
R166  240  [R0402]  51.36 42.4 270 top
R167  4.7K  [R0402]  34.09 47.99 270 top
R168  4.7K  [R0402]  35.61 47.99 270 top
R169  4.7K  [R0402]  33.83 42.4 90 top
R172  130  [R0402]  35.99 50.53 180 top
R175  39  [R0603]  22.4 53.07 90 bottom
R176  8.06K  [R0402]  18.47 49.89 270 top
R178  10K  [R0402]  13.26 55.1 0 bottom
R191  1K  [R0402]  44.5 14.46 270 top
R194  1K  [R0402]  43.36 14.46 90 top
R221  10K  [R0402]  44.38 59.67 270 bottom
R222  10K  [R0402]  43.23 59.67 270 bottom
R301  10  [R0201]  27.36 5.06 90 top
R304  10K  [R0201]  27.56 6.33 270 top
R306  10K  [R0201]  84.63 7.6 0 top
RXA  U.FL-R-SMT-1(01)  [CNHIROSE-U_FL-R-SMT-1]  96.45 26.52 270 top
RXB  U.FL-R-SMT-1(01)  [CNHIROSE-U_FL-R-SMT-1]  96.45 15.09 270 top
S1  CAS-120TB  [SWSML213W98H98]  3.74 9.76 0 top
S3  CAS-120TB  [SWSML213W98H98]  52.88 54.46 0 top
S4  CAS-120TB  [SWSML213W98H98]  46.79 54.46 0 top
SW1  7914J-1-000E  [SWSMSQ197H165]  38.03 4.43 180 top
T1  TCM1-63AX+  [TSML150W160H160]  77.73 25.25 300 top
T2  TCM1-63AX+  [TSML150W160H160]  77.62 34.75 270 top
T3  TCM1-63AX+  [TSML150W160H160]  69.9 20.3 270 top
T4  TCM1-63AX+  [TSML150W160H160]  77.51 40.98 295 top
TP2  TESTPAD  [TPSMC30]  53.96 7.92 0 top
TXA  U.FL-R-SMT-1(01)  [CNHIROSE-U_FL-R-SMT-1]  96.45 37.95 270 top
TXB  U.FL-R-SMT-1(01)  [CNHIROSE-U_FL-R-SMT-1]  96.45 49.38 270 top
TXM  U.FL-R-SMT-1(01)  [CNHIROSE-U_FL-R-SMT-1]  91.37 32.24 270 top
U1  XC7Z020-1CLG400I  [BGA400]  29.14 30.59 180 top
U2  MT41K256M16TW-107 IT:P  [FBGA96_C]  46.03 24.37 90 bottom
U3  MT41K256M16TW-107 IT:P  [FBGA96_C]  46.03 41.13 90 bottom
U4  ADP2114ACPZ  [QFN32_5X5_PAD3_1X3_1]  66.98 4.73 0 top
U5  ADG772BCPZ  [QFN10_1_6X1_3]  78.28 57.51 0 top
U6  ADP7102ACPZ-2.5  [QFN8_3X3_PAD2_44X1_7]  79.3 57.89 270 bottom
U7  ADM7160AUJZ-1.8  [TSOT-5]  78.16 54.08 90 bottom
U9  ADP7104ACPZ-3.3  [DFN8_3X3_PAD2_38X1_64]  39.04 53.19 270 top
U10  88E1512-56QFN  [QFN56_8X8_PAD4_37X4_37]  21.64 7.09 180 bottom
U11  TXS02612RTWR  [QFN24_4X4_PAD2_5X2_5]  7.8 14.59 90 top
U13  MT25QU256ABA8E12-1SIT  [TBGA24]  67.62 56.62 180 top
U14  TPS51206DSQR  [SON10_2X2_PAD1_5X0_9]  46.92 59.42 270 bottom
U15  USB3320C-EZK  [QFN32_5X5_PAD3_3X3_3]  22.91 52.94 90 top
U16  CDSOT23-SR208  [SOT23_6-2]  15.55 53.07 180 top
U17  AD9364BBCZ  [BGA144-2]  65.2 29.69 0 top
U18  ADP2164ACPZ  [QFN16_4X4_PAD2_5X2_5]  22.79 6.33 90 top
U19  ADP1754ACPZ-1.3  [QFN16_4X4_PAD2_1X2_1]  79.94 9 0 top
U20  ADP1754ACPZ-1.3  [QFN16_4X4_PAD2_1X2_1]  89.59 9 0 top
U21  TCA9517DGKR  [MSOP8]  3.99 23.35 180 bottom
U22  FXL4T245BQX  [DQFN14_3X2_5_PAD1_65X1_15]  56.69 31.48 90 top
U24  AD7291BCPZ  [QFN20_4X4_PAD2_6X2_6]  76.13 44.94 180 bottom
W1  WP45  [TPC75D45]  75.24 14.33 0 top
Y1  33.333MEGHZ  [YSML98W79H35]  46.86 6.57 90 top
Y2  25MEGHZ  [YSML126W98H39]  33.33 12.81 0 top
Y3  24MEGHZ  [YSML98W79H35]  17.71 57.13 270 top
Y4  40MEGHz  [YSML126W98H47]  76.63 52.56 90 top

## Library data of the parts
C1 C2 = CAP: Tolerance: 20; User Part Number: UPN; alternate symbols: (); part number: CAP_SM-100UF,6.3V,20,E016591,C1206H71; tolerance: 20; signal model: DEFAULT_CAPACITOR_100000pF_1_2
C3 = CAP: alternate symbols: (); part number: CAP_SM-4.7UF,6.3V,10,E020089,C0402; tolerance: 10; signal model: DEFAULT_CAPACITOR_100000pF_1_2
C4 C31 C33 C49 C50 C52 C63 C70 C74 C86 C87 C101 C106 C120 C121 C133 C140 C141 C159 C167 C169 C174 C175 C218 = CAP: alternate symbols: (); part number: CAP_SM-4.7UF,6.3V,10,E020089,C0402; tolerance: 10
C5 C152 = CAP: Tolerance: 10; User Part Number: UPN; alternate symbols: (); part number: CAP_SM-4.7UF,16V,10,E020112,C0603; tolerance: 10
C6 C93 C104 = CAP: alternate symbols: (); part number: CAP_SM-0.001UF,25V,10,E006762,C0201; tolerance: 10
C7 C35 C44 C46-C48 C51 C53 C72 C88 C89 C107 C108 C125 C143 C162 C163 C170 C171 C178 C179 C189 = CAP: alternate symbols: (); part number: CAP_SM-0.47UF,10V,10,E007611,C0402; tolerance: 10
C8 C9 C25 = CAP: alternate symbols: (); part number: CAP_SM-18PF,50V,5,E028398,C0201; tolerance: 5; signal model: DEFAULT_CAPACITOR_100000pF_1_2
C10 C11 C15-C20 C22 C23 = CAP: alternate symbols: (); part number: CAP_SM-0.47UF,10V,10,E007611,C0402; tolerance: 10; signal model: DEFAULT_CAPACITOR_100000pF_1_2
C12 = CAP: alternate symbols: (); part number: CAP_SM-1UF,6.3V,10,E011561,C0402; tolerance: 10; signal model: DEFAULT_CAPACITOR_100000pF_1_2
C13 C14 = CAP: alternate symbols: (); part number: CAP_SM-0.001UF,25V,10,E006762,C0201; tolerance: 10; signal model: DEFAULT_CAPACITOR_100000pF_1_2
C21 = CAP: Tolerance: 20; User Part Number: UPN; alternate symbols: (); part number: CAP_SM-10UF,6.3V,20,E007143,C0603; tolerance: 20; signal model: DEFAULT_CAPACITOR_100000pF_1_2
C24 = CAP: Tolerance: 20; User Part Number: UPN; alternate symbols: (); part number: CAP_SM-22UF,10V,20,E022680,C0603; tolerance: 20; signal model: DEFAULT_CAPACITOR_100000pF_1_2
C26 = CAP: alternate symbols: (); part number: CAP_SM-18PF,50V,5,E028398,C0201; tolerance: 5; signal model: DEFAULT_CAPACITOR_18.000000pF_1_2
C27-C29 C56 C100 C138 C151 C173 = CAP: Tolerance: 20; User Part Number: UPN; alternate symbols: (); part number: CAP_SM-100UF,6.3V,20,E016591,C1206H71; tolerance: 20
C30 C71 C145 = CAP: Tolerance: 20; User Part Number: UPN; alternate symbols: (); part number: CAP_SM-22UF,10V,20,E022680,C0603; tolerance: 20
C32 C34 C111 C126 = CAP: Tolerance: 10; User Part Number: UPN; alternate symbols: (); part number: CAP_SM-0.1UF,25V,10,E007204,C0603; tolerance: 10
C36 C58 C78 C181-C183 C199 C219 = CAP: Tolerance: 10; User Part Number: UPN; alternate symbols: (); part number: CAP_SM-1UF,16V,10,E020111,C0603; tolerance: 10
C37 C45 C137 C139 = CAP: Tolerance: 10; User Part Number: UPN; alternate symbols: (); part number: CAP_SM-10UF,16V,10,E006166,C0805H53; tolerance: 10
C38 C98 C124 C134 C147 C158 C191 C193-C198 C200 C210 C312 C313 C341 C342 C363 C365 = CAP: Tolerance: 20; User Part Number: UPN; alternate symbols: (); part number: CAP_SM-10UF,6.3V,20,E007143,C0603; tolerance: 20
C39 C42 C54 C55 C57 C73 C75 C190 C201 C203 C206 C208 C211 C212 C217 C224-C226 C242 = CAP: alternate symbols: (); part number: CAP_SM-0.1UF,16V,10,E018707,C0402; tolerance: 10
C40 C41 C214 = CAP: alternate symbols: (); part number: CAP_SM-0.1UF,16V,10,E018707,C0402; tolerance: 10; signal model: DEFAULT_CAPACITOR_100000pF_1_2
C43 C76 C77 C84 C102 C103 C122 C123 C311 C321 C322 C325 C326 C329 C330 C333 C334 C340 C355 C356 C360 = CAP: alternate symbols: (); part number: CAP_SM-0.01UF,10V,10,E007201,C0201; tolerance: 10
C59 C60 = CAP: Tolerance: 5; User Part Number: UPN; alternate symbols: (); part number: CAP_SM-27PF,50V,5,E000395,C0603; tolerance: 5
C61 = CAP: alternate symbols: (); part number: CAP_SM-0.1UF,16V,10,E027519,C0402; tolerance: 10
C62 R3 R6 R9 R12 R161 = RES: alternate symbols: (R0402L); part number: RES_SM-0,E010661,1/16W,1,R0402; tolerance: 1
C64 C65 = CAP: Tolerance: 20; User Part Number: UPN; alternate symbols: (); part number: CAP_SM-22UF,10V,20,E014683,C0805H60; tolerance: 20
C66 = CAP: Tolerance: 20; User Part Number: UPN; alternate symbols: (); part number: CAP_SM-47UF,10V,20,E022064,C0805H60; tolerance: 20
C67 = CAP: alternate symbols: (); part number: CAP_SM-150PF,50V,5,E012646,C0402; tolerance: 5
C68 = CAP: alternate symbols: (); part number: CAP_SM-180PF,50V,5,E033222,C0402; tolerance: 5
C69 = CAP: alternate symbols: C0402; part number: CAP_SM-5.6NF,50V,5,E033450,C0402H22; tolerance: 5
C79 C82 C83 = CAP: Tolerance: 20; User Part Number: UPN; alternate symbols: (); part number: CAP_SM-10UF,25V,20,E015584,C0805H60; tolerance: 20
C80 = CAP: alternate symbols: C0402; part number: CAP_SM-15NF,50V,10,E033451,C0402H22; tolerance: 10
C81 = CAP: Tolerance: 10; User Part Number: UPN; alternate symbols: (); part number: CAP_SM-0.22UF,16V,10,E000443,C0805; tolerance: 10
C85 C90 C99 C110 = CAP: alternate symbols: (); part number: CAP_SM-18PF,50V,5,E028398,C0201; tolerance: 5
C91 C92 C94-C97 C109 C112 C115-C118 = CAP: alternate symbols: (); part number: CAP_SM-0.1UF,16V,20,E017331,C0201; tolerance: 20
C105 C320 C323 C324 C327 C328 C331 C332 C335 C354 C357 C358 C361 = CAP: alternate symbols: (); part number: CAP_SM-1UF,6.3V,10,E011561,C0402; tolerance: 10
C113 C188 C243-C246 C314 C315 C319 C343 C344 C364 = CAP: alternate symbols: (); part number: CAP_SM-0.1UF,6.3V,10,E011567,C0201; tolerance: 10
C114 = CAP: alternate symbols: (); part number: CAP_SM-0.0033UF,50V,10,E007461,C0402; tolerance: 10
C119 C128-C132 C135 C136 C251 = CAP: Tolerance: 20; User Part Number: UPN; alternate symbols: (C0805L); part number: CAP_SM-47UF,6.3V,20,E008247,C0805H60; tolerance: 20
C127 = CAP: alternate symbols: (); part number: CAP_SM-56000PF,16V,0.1,E019786,C0402; tolerance: 0.1
C142 C144 = CAP: alternate symbols: (); part number: CAP_SM-0.047UF,25V,10,E025704,C0402; tolerance: 10
C146 = CAP: alternate symbols: (); part number: CAP_SM-1UF,10V,20,E017007,C0402; tolerance: 20
C148 C149 = CAP: alternate symbols: (); part number: CAP_SM-10UF,10V,20,E020928,C0402; tolerance: 20
C150 = CAP: Tolerance: 10; User Part Number: UPN; alternate symbols: (); part number: CAP_SM-0.047UF,50V,10,E018461,C0603; tolerance: 10
C165 C216 = CAP: alternate symbols: (); part number: CAP_SM-18PF,50V,5,E007476,C0402; tolerance: 5
C184 = CAP: Tolerance: 10; User Part Number: UPN; alternate symbols: (); part number: CAP_SM-1UF,16V,10,E020111,C0603; tolerance: 10; signal model: DEFAULT_CAPACITOR_100000pF_1_2
D3 D4 = DIOLED: Tolerance: N/A; User Part Number: UPN; alternate symbols: (); part number: DIOLED_SM-QTLP600C4TR,2.1V,N/A,E025710,LED0603; tolerance: N/A
E1 E12 = FERRITE: Tolerance: 25; User Part Number: UPN; alternate symbols: (); part number: FERRITE_SM-220OHM,25,E017491,L0805; tolerance: 25
E2-E9 E11 E14-E16 = FERRITE: Tolerance: 25; User Part Number: UPN; alternate symbols: (); part number: FERRITE_SM-100OHM,25,E012241,L0805; tolerance: 25
E10 = FERRITE: Tolerance: 25; User Part Number: UPN; alternate symbols: (); part number: FERRITE_SM-75OHM,25,E017348,L0402; tolerance: 25
J3 = CN9P_4GND: User Part Number: UPN; Tolerance: N/A; alternate symbols: (); part number: CN9P_4GND_SM-DM3CS-SF,E022379,CNHIROSEDM3CS-SF; tolerance: N/A
JP1-JP4 = NC3P_JMPR: Tolerance: N/A; User Part Number: UPN; alternate symbols: (); part number: NC3P_JMPR_SM-3PIN_SOLDER_JUMPER,E005606,JPRSLD03; tolerance: N/A
JX1-JX4 = CN100P_ODD_EVEN: User Part Number: UPN; Tolerance: N/A; alternate symbols: (); part number: CN100P_ODD_EVEN_SM-61082-101400LF,E022296,CNFCI61082-101400; tolerance: N/A
L1 L2 L8 L9 = IND: Tolerance: 5; User Part Number: UPN; alternate symbols: L0402L; part number: IND_SM-330NH,5,E028124,L0402; tolerance: 5
L3 L4 = IND: User Part Number: UPN; Tolerance: 20; alternate symbols: (); part number: IND_SM-1.5UH,20,E017267,LSMSQ157H83; tolerance: 20
L5 = IND: User Part Number: UPN; Tolerance: 20; alternate symbols: (); part number: IND_SM-1UH,20,E015845,LSMSQ157H83; tolerance: 20
L6 = IND: Tolerance: 20; User Part Number: UPN; alternate symbols: (); part number: IND_SM-150NH,20,E026966,L1008_A; tolerance: 20
L7 L10 = IND: User Part Number: UPN; Tolerance: 20; alternate symbols: (); part number: IND_SM-180NH,20,E026052,LSMSQ79H41; tolerance: 20
L12 = FERRITE: Tolerance: 25; User Part Number: UPN; alternate symbols: (); part number: FERRITE_SM-600OHMS,25,E007179,L0603; tolerance: 25
L302 = IND: User Part Number: UPN; Tolerance: 30; alternate symbols: (); part number: IND_SM-0.47UH,30,E018627,L1210H67; tolerance: 30
M1 = MODLT15CCC2243A: Tolerance: N/A; User Part Number: UPN; alternate symbols: (); part number: MODLT15CCC2243A_SM-LT15CCC2243A,E023383,MLT15CCC2243A; tolerance: N/A
Q1-Q4 = TRANBSS138: User Part Number: UPN; Tolerance: N/A; alternate symbols: (); part number: TRANBSS138_SM-BSS138TA,E004635,SOT23; tolerance: N/A
Q5 Q6 Q14 = TRANNMOSFET_V8: User Part Number: UPN; Tolerance: N/A; alternate symbols: (); part number: TRANNMOSFET_V8_SM-BSS138LT1G,E018770,SOT23; tolerance: N/A
R1 R23 R301 = RES: alternate symbols: (); part number: RES_SM-10,E013982,1/20W,1,R0201; tolerance: 1
R2 R123 = RES: alternate symbols: (); part number: RES_SM-1,E014056,1/20W,1,R0201
R4 = RES: alternate symbols: (R0402L); part number: RES_SM-4.99K,E006643,1/16W,1,R0402; tolerance: 1; signal model: DEFAULT_RESISTOR_0.001OHM_1_2
R5 R101 = RES: alternate symbols: (); part number: RES_SM-49.9,E007693,1/20W,1,R0201; tolerance: 1
R7 R26 R27 R37 R40 R41 R46 R47 R178 R221 R222 = RES: alternate symbols: (R0402L,R0402L_ALT); part number: RES_SM-10K,E003751,1/10W,1,R0402; tolerance: 1
R8 = RES: alternate symbols: (R0402L,R0402L_ALT); part number: RES_SM-10K,E003751,1/10W,1,R0402; tolerance: 1; signal model: DEFAULT_RESISTOR_0.001OHM_1_2
R10 = RES: alternate symbols: (R0402L); part number: RES_SM-27.4K,E021819,1/10W,1,R0402; tolerance: 1
R11 R50 R109 = RES: alternate symbols: (R0402L); part number: RES_SM-4.99K,E006643,1/16W,1,R0402; tolerance: 1
R13 R14 = RES: alternate symbols: (R0402L,R0402L_ALT); part number: RES_SM-1K,E003763,1/10W,1,R0402; tolerance: 1; signal model: DEFAULT_RESISTOR_100.000000OHM_1_2
R15 R49 R55 R59 R191 R194 = RES: alternate symbols: (R0402L,R0402L_ALT); part number: RES_SM-1K,E003763,1/10W,1,R0402; tolerance: 1
R16 = RES: alternate symbols: (R0402L,R0402L_ALT); part number: RES_SM-1K,E003763,1/10W,1,R0402; tolerance: 1; signal model: DEFAULT_RESISTOR_0.001OHM_1_2
R17 R18 = RES: alternate symbols: (R0402L); part number: RES_SM-220,E011432,1/16W,1,R0402; tolerance: 1
R19 = RES: alternate symbols: (R0402L,R0402L_ALT); part number: RES_SM-0,E003438,N/A,5,R0402; tolerance: 5
R20 = RES: alternate symbols: (R0402L); part number: RES_SM-4.75K,E006813,1/16W,1,R0402; tolerance: 1
R22 R25 R33 R43 R56 R63-R66 R111 R304 R306 = RES: alternate symbols: (); part number: RES_SM-10K,E004011,1/20W,1,R0201; tolerance: 1
R28 R134 R135 R165 R166 = RES: alternate symbols: (R0402L,R0402L_ALT); part number: RES_SM-240,E010877,1/16W,1,R0402; tolerance: 1
R29 = RES: alternate symbols: (R0402L); part number: RES_SM-30K,E017958,1/16W,1,R0402; tolerance: 1
R31 R32 = RES: alternate symbols: (); part number: RES_SM-20K,E004013,1/20W,1,R0201; tolerance: 1
R34 = RES: alternate symbols: (R0402L); part number: RES_SM-15K,E007441,1/16W,1,R0402; tolerance: 1
R35 = RES: alternate symbols: (R0402L); part number: RES_SM-18.7K,E010018,1/16W,1,R0402; tolerance: 1
R36 R116 R119-R122 = RES: alternate symbols: (R0402L,R0402L_ALT); part number: RES_SM-20K,E003791,1/16W,1,R0402; tolerance: 1
R38 = RES: alternate symbols: (R0402L); part number: RES_SM-44.2K,E023712,1/10W,1,R0402; tolerance: 1
R39 = RES: alternate symbols: (R0402L); part number: RES_SM-46.4K,E011115,1/16W,1,R0402; tolerance: 1
R42 R44 R57 R58 R167-R169 = RES: alternate symbols: (R0402L,R0402L_ALT); part number: RES_SM-4.7K,E008190,1/10W,1,R0402; tolerance: 1
R45 = RES: alternate symbols: (R0402L); part number: RES_SM-23.2K,E019517,1/16W,1,R0402; tolerance: 1
R48 = RES: Tolerance: 0.5; User Part Number: UPN; alternate symbols: (R0603L); part number: RES_SM-19.6K,E012200,1/16W,0.5,R0603; tolerance: 0.5
R53 R133 = RES: alternate symbols: (); part number: RES_SM-1K,E004010,1/20W,1,R0201; tolerance: 1
R54 = RES: alternate symbols: (R0402L); part number: RES_SM-301,E011195,1/16W,1,R0402; tolerance: 1
R61 R62 R67 R68 = RES: alternate symbols: (); part number: RES_SM-4.02K,E023201,1/20W,1,R0201; tolerance: 1
R113 R172 = RES: alternate symbols: (R0402L); part number: RES_SM-130,E003795,1/16W,1,R0402; tolerance: 1
R114 R175 = RES: Tolerance: 1; User Part Number: UPN; alternate symbols: (); part number: RES_SM-39,E004235,1/16W,1,R0603; tolerance: 1
R125 = RES: alternate symbols: (); part number: RES_SM-14.3K,E014068,1/20W,1,R0201; tolerance: 1
R136-R141 R143-R156 R159 R160 R162 R163 = RES: alternate symbols: (); part number: RES_SM-120,E011549,1/20W,1,R0201; tolerance: 1
R142 = RES: alternate symbols: (R0402L,R0402L_ALT); part number: RES_SM-80.6,E022369,1/16W,0.1,R0402; tolerance: 0.1
R176 = RES: alternate symbols: (R0402L); part number: RES_SM-8.06K,E021385,1/10W,1,R0402; tolerance: 1
RXA RXB TXA TXB TXM = CNBNC3P: Tolerance: N/A; User Part Number: UPN; alternate symbols: (); part number: CNBNC3P_SM-U.FL-R-SMT-1(01),E022198,CNHIROSE-U_FL-R-SMT-1; tolerance: N/A
S1 S3 S4 = SWSPDT_V2: Tolerance: N/A; User Part Number: UPN; alternate symbols: (); part number: SWSPDT_V2_SM-CAS-120TB,E012554,SWSML213W98H98; tolerance: N/A
SW1 = SWSPST4PIN_V2: User Part Number: UPN; Tolerance: N/A; alternate symbols: (); part number: SWSPST4PIN_V2_SM-7914J-1-000E,E011086,SWSMSQ197H165; tolerance: N/A
T1-T4 = XFMRTCMXXXX_V3: Tolerance: N/A; User Part Number: UPN; alternate symbols: (); part number: XFMRTCMXXXX_V3_SM-TCM1-63AX+,E018203,TSML150W160H160; tolerance: N/A
TP2 = NCTESTPAD: Tolerance: N/A; User Part Number: UPN; alternate symbols: (); part number: NCTESTPAD_SM-TESTPAD,E012884,TPSMC30; tolerance: N/A
U1 = ICXC7Z20: User Part Number: UPN; Tolerance: N/A; alternate symbols: (); part number: ICXC7Z20_SM-XC7Z020-1CLG400I,E025595,BGA400; tolerance: N/A
U2 U3 = ICMT41K256M16: User Part Number: UPN; Tolerance: N/A; alternate symbols: (); part number: ICMT41K256M16_SM-MT41K256M16TW-107 IT:P,E025601,FBGA96_C; tolerance: N/A
U4 = ADP2114: User Part Number: UPN; Tolerance: N/A; alternate symbols: (); part number: ADP2114_SM-ADP2114ACPZ,E008105,QFN32_5X5_PAD3_1X3_1; tolerance: N/A
U5 = ADG772: User Part Number: UPN; Tolerance: N/A; alternate symbols: (); part number: ADG772_SM-ADG772BCPZ,E010354,QFN10_1_6X1_3; tolerance: N/A
U6 = ADP7102: Tolerance: N/A; User Part Number: UPN; alternate symbols: (); part number: ADP7102_SM-ADP7102ACPZ-2.5,E021467,QFN8_3X3_PAD2_44X1_7; tolerance: N/A
U7 = ADM7160: User Part Number: UPN; Tolerance: N/A; alternate symbols: (); part number: ADM7160_SM-ADM7160AUJZ-1.8,E018469,TSOT-5; tolerance: N/A
U9 = ADP7104: Tolerance: N/A; User Part Number: UPN; alternate symbols: (); part number: ADP7104_SM-ADP7104ACPZ-3.3,E014912,DFN8_3X3_PAD2_38X1_64; tolerance: N/A
U10 = IC88E151X: User Part Number: UPN; Tolerance: N/A; alternate symbols: (); part number: IC88E151X_SM-88E1512-56QFN,E018914,QFN56_8X8_PAD4_37X4_37; tolerance: N/A
U11 = ICTXS02612RTW: User Part Number: UPN; Tolerance: N/A; alternate symbols: (); part number: ICTXS02612RTW_SM-TXS02612RTWR,E021332,QFN24_4X4_PAD2_5X2_5; tolerance: N/A
U13 = ICMT25Q: User Part Number: UPN; Tolerance: N/A; alternate symbols: (); part number: ICMT25Q_SM-MT25QU256ABA8E12-1SIT,E027529,TBGA24; tolerance: N/A
U14 = ICTPS51206: Tolerance: N/A; User Part Number: UPN; alternate symbols: (); part number: ICTPS51206_SM-TPS51206DSQR,E021346,SON10_2X2_PAD1_5X0_9; tolerance: N/A
U15 = ICUSB3320C: Tolerance: N/A; User Part Number: UPN; alternate symbols: (); part number: ICUSB3320C_SM-USB3320C-EZK,E021334,QFN32_5X5_PAD3_3X3_3; tolerance: N/A
U16 = DIO6P_V8: User Part Number: UPN; Tolerance: N/A; alternate symbols: (); part number: DIO6P_V8_SM-CDSOT23-SR208,20V,N/A,E021337,SOT23_6-2; tolerance: N/A
U17 = AD9364: alternate symbols: (); part number: AD9364_SM-AD9364BBCZ,E019869,BGA144-2; tolerance: N/A
U18 = ADP2164: Tolerance: N/A; User Part Number: UPN; alternate symbols: (); part number: ADP2164_SM-ADP2164ACPZ,E013699,QFN16_4X4_PAD2_5X2_5; tolerance: N/A
U19 U20 = ADP1754: Tolerance: N/A; User Part Number: UPN; alternate symbols: (); part number: ADP1754_SM-ADP1754ACPZ-1.3,E022696,QFN16_4X4_PAD2_1X2_1; tolerance: N/A
U21 = CMOSTCA9517: Tolerance: N/A; User Part Number: UPN; alternate symbols: (); part number: CMOSTCA9517_SM-TCA9517DGKR,E022173,MSOP8; tolerance: N/A
U22 = ICFXL4T245: Tolerance: N/A; User Part Number: UPN; alternate symbols: (); part number: ICFXL4T245_SM-FXL4T245BQX,E021654,DQFN14_3X2_5_PAD1_65X1_15; tolerance: N/A
U24 = AD7291: User Part Number: UPN; Tolerance: N/A; alternate symbols: (); part number: AD7291_SM-AD7291BCPZ,E017361,QFN20_4X4_PAD2_6X2_6; tolerance: N/A
W1 = NCWP: Tolerance: N/A; User Part Number: UPN; alternate symbols: (); part number: NCWP_TH-WP45,E002516,TPC75D45; tolerance: N/A
Y1 = XTALOSC4P_V7: Tolerance: N/A; User Part Number: UPN; alternate symbols: (); part number: XTALOSC4P_V7_SM-33.333MEGHZ,E024048,YSML98W79H35; tolerance: N/A
Y2 = XTAL4PIN_V3: Tolerance: +/-20PPM; User Part Number: UPN; alternate symbols: (); part number: XTAL4PIN_V3_SM-25MEGHZ,E023420,YSML126W98H39; tolerance: +/-20PPM
Y3 = XTALOSC4P_V7: Tolerance: N/A; User Part Number: UPN; alternate symbols: (); part number: XTALOSC4P_V7_SM-24MEGHZ,E022374,YSML98W79H35; tolerance: N/A
Y4 = XTALOSC4P_V21: Tolerance: N/A; User Part Number: UPN; alternate symbols: (); part number: XTALOSC4P_V21_SM-40MEGHZ,E020493,YSML126W98H47; tolerance: N/A

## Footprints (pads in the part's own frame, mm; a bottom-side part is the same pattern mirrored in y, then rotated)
BGA144-2
  round 0.356 smd: A1(-4.4,-4.4) A2(-4.4,-3.6) A3(-4.4,-2.8) A4(-4.4,-2) A5(-4.4,-1.2) A6(-4.4,-0.4) A7(-4.4,0.4) A8(-4.4,1.2) A9(-4.4,2) A10(-4.4,2.8) A11(-4.4,3.6) A12(-4.4,4.4) B1(-3.6,-4.4) B2(-3.6,-3.6) B3(-3.6,-2.8) B4(-3.6,-2) B5(-3.6,-1.2) B6(-3.6,-0.4) B7(-3.6,0.4) B8(-3.6,1.2) B9(-3.6,2) B10(-3.6,2.8) B11(-3.6,3.6) B12(-3.6,4.4) C1(-2.8,-4.4) C2(-2.8,-3.6) C3(-2.8,-2.8) C4(-2.8,-2) C5(-2.8,-1.2) C6(-2.8,-0.4) C7(-2.8,0.4) C8(-2.8,1.2) C9(-2.8,2) C10(-2.8,2.8) C11(-2.8,3.6) C12(-2.8,4.4) D1(-2,-4.4) D2(-2,-3.6) D3(-2,-2.8) D4(-2,-2) D5(-2,-1.2) D6(-2,-0.4) D7(-2,0.4) D8(-2,1.2) D9(-2,2) D10(-2,2.8) D11(-2,3.6) D12(-2,4.4) E1(-1.2,-4.4) E2(-1.2,-3.6) E3(-1.2,-2.8) E4(-1.2,-2) E5(-1.2,-1.2) E6(-1.2,-0.4) E7(-1.2,0.4) E8(-1.2,1.2) E9(-1.2,2) E10(-1.2,2.8) E11(-1.2,3.6) E12(-1.2,4.4) F1(-0.4,-4.4) F2(-0.4,-3.6) F3(-0.4,-2.8) F4(-0.4,-2) F5(-0.4,-1.2) F6(-0.4,-0.4) F7(-0.4,0.4) F8(-0.4,1.2) F9(-0.4,2) F10(-0.4,2.8) F11(-0.4,3.6) F12(-0.4,4.4) G1(0.4,-4.4) G2(0.4,-3.6) G3(0.4,-2.8) G4(0.4,-2) G5(0.4,-1.2) G6(0.4,-0.4) G7(0.4,0.4) G8(0.4,1.2) G9(0.4,2) G10(0.4,2.8) G11(0.4,3.6) G12(0.4,4.4) H1(1.2,-4.4) H2(1.2,-3.6) H3(1.2,-2.8) H4(1.2,-2) H5(1.2,-1.2) H6(1.2,-0.4) H7(1.2,0.4) H8(1.2,1.2) H9(1.2,2) H10(1.2,2.8) H11(1.2,3.6) H12(1.2,4.4) J1(2,-4.4) J2(2,-3.6) J3(2,-2.8) J4(2,-2) J5(2,-1.2) J6(2,-0.4) J7(2,0.4) J8(2,1.2) J9(2,2) J10(2,2.8) J11(2,3.6) J12(2,4.4) K1(2.8,-4.4) K2(2.8,-3.6) K3(2.8,-2.8) K4(2.8,-2) K5(2.8,-1.2) K6(2.8,-0.4) K7(2.8,0.4) K8(2.8,1.2) K9(2.8,2) K10(2.8,2.8) K11(2.8,3.6) K12(2.8,4.4) L1(3.6,-4.4) L2(3.6,-3.6) L3(3.6,-2.8) L4(3.6,-2) L5(3.6,-1.2) L6(3.6,-0.4) L7(3.6,0.4) L8(3.6,1.2) L9(3.6,2) L10(3.6,2.8) L11(3.6,3.6) L12(3.6,4.4) M1(4.4,-4.4) M2(4.4,-3.6) M3(4.4,-2.8) M4(4.4,-2) M5(4.4,-1.2) M6(4.4,-0.4) M7(4.4,0.4) M8(4.4,1.2) M9(4.4,2) M10(4.4,2.8) M11(4.4,3.6) M12(4.4,4.4)
BGA400
  round 0.406 smd: A1(-7.6,-7.6) A2(-7.6,-6.8) A3(-7.6,-6) A4(-7.6,-5.2) A5(-7.6,-4.4) A6(-7.6,-3.6) A7(-7.6,-2.8) A8(-7.6,-2) A9(-7.6,-1.2) A10(-7.6,-0.4) A11(-7.6,0.4) A12(-7.6,1.2) A13(-7.6,2) A14(-7.6,2.8) A15(-7.6,3.6) A16(-7.6,4.4) A17(-7.6,5.2) A18(-7.6,6) A19(-7.6,6.8) A20(-7.6,7.6) B1(-6.8,-7.6) B2(-6.8,-6.8) B3(-6.8,-6) B4(-6.8,-5.2) B5(-6.8,-4.4) B6(-6.8,-3.6) B7(-6.8,-2.8) B8(-6.8,-2) B9(-6.8,-1.2) B10(-6.8,-0.4) B11(-6.8,0.4) B12(-6.8,1.2) B13(-6.8,2) B14(-6.8,2.8) B15(-6.8,3.6) B16(-6.8,4.4) B17(-6.8,5.2) B18(-6.8,6) B19(-6.8,6.8) B20(-6.8,7.6) C1(-6,-7.6) C2(-6,-6.8) C3(-6,-6) C4(-6,-5.2) C5(-6,-4.4) C6(-6,-3.6) C7(-6,-2.8) C8(-6,-2) C9(-6,-1.2) C10(-6,-0.4) C11(-6,0.4) C12(-6,1.2) C13(-6,2) C14(-6,2.8) C15(-6,3.6) C16(-6,4.4) C17(-6,5.2) C18(-6,6) C19(-6,6.8) C20(-6,7.6) D1(-5.2,-7.6) D2(-5.2,-6.8) D3(-5.2,-6) D4(-5.2,-5.2) D5(-5.2,-4.4) D6(-5.2,-3.6) D7(-5.2,-2.8) D8(-5.2,-2) D9(-5.2,-1.2) D10(-5.2,-0.4) D11(-5.2,0.4) D12(-5.2,1.2) D13(-5.2,2) D14(-5.2,2.8) D15(-5.2,3.6) D16(-5.2,4.4) D17(-5.2,5.2) D18(-5.2,6) D19(-5.2,6.8) D20(-5.2,7.6) E1(-4.4,-7.6) E2(-4.4,-6.8) E3(-4.4,-6) E4(-4.4,-5.2) E5(-4.4,-4.4) E6(-4.4,-3.6) E7(-4.4,-2.8) E8(-4.4,-2) E9(-4.4,-1.2) E10(-4.4,-0.4) E11(-4.4,0.4) E12(-4.4,1.2) E13(-4.4,2) E14(-4.4,2.8) E15(-4.4,3.6) E16(-4.4,4.4) E17(-4.4,5.2) E18(-4.4,6) E19(-4.4,6.8) E20(-4.4,7.6) F1(-3.6,-7.6) F2(-3.6,-6.8) F3(-3.6,-6) F4(-3.6,-5.2) F5(-3.6,-4.4) F6(-3.6,-3.6) F7(-3.6,-2.8) F8(-3.6,-2) F9(-3.6,-1.2) F10(-3.6,-0.4) F11(-3.6,0.4) F12(-3.6,1.2) F13(-3.6,2) F14(-3.6,2.8) F15(-3.6,3.6) F16(-3.6,4.4) F17(-3.6,5.2) F18(-3.6,6) F19(-3.6,6.8) F20(-3.6,7.6) G1(-2.8,-7.6) G2(-2.8,-6.8) G3(-2.8,-6) G4(-2.8,-5.2) G5(-2.8,-4.4) G6(-2.8,-3.6) G7(-2.8,-2.8) G8(-2.8,-2) G9(-2.8,-1.2) G10(-2.8,-0.4) G11(-2.8,0.4) G12(-2.8,1.2) G13(-2.8,2) G14(-2.8,2.8) G15(-2.8,3.6) G16(-2.8,4.4) G17(-2.8,5.2) G18(-2.8,6) G19(-2.8,6.8) G20(-2.8,7.6) H1(-2,-7.6) H2(-2,-6.8) H3(-2,-6) H4(-2,-5.2) H5(-2,-4.4) H6(-2,-3.6) H7(-2,-2.8) H8(-2,-2) H9(-2,-1.2) H10(-2,-0.4) H11(-2,0.4) H12(-2,1.2) H13(-2,2) H14(-2,2.8) H15(-2,3.6) H16(-2,4.4) H17(-2,5.2) H18(-2,6) H19(-2,6.8) H20(-2,7.6) J1(-1.2,-7.6) J2(-1.2,-6.8) J3(-1.2,-6) J4(-1.2,-5.2) J5(-1.2,-4.4) J6(-1.2,-3.6) J7(-1.2,-2.8) J8(-1.2,-2) J9(-1.2,-1.2) J10(-1.2,-0.4) J11(-1.2,0.4) J12(-1.2,1.2) J13(-1.2,2) J14(-1.2,2.8) J15(-1.2,3.6) J16(-1.2,4.4) J17(-1.2,5.2) J18(-1.2,6) J19(-1.2,6.8) J20(-1.2,7.6) K1(-0.4,-7.6) K2(-0.4,-6.8) K3(-0.4,-6) K4(-0.4,-5.2) K5(-0.4,-4.4) K6(-0.4,-3.6) K7(-0.4,-2.8) K8(-0.4,-2) K9(-0.4,-1.2) K10(-0.4,-0.4) K11(-0.4,0.4) K12(-0.4,1.2) K13(-0.4,2) K14(-0.4,2.8) K15(-0.4,3.6) K16(-0.4,4.4) K17(-0.4,5.2) K18(-0.4,6) K19(-0.4,6.8) K20(-0.4,7.6) L1(0.4,-7.6) L2(0.4,-6.8) L3(0.4,-6) L4(0.4,-5.2) L5(0.4,-4.4) L6(0.4,-3.6) L7(0.4,-2.8) L8(0.4,-2) L9(0.4,-1.2) L10(0.4,-0.4) L11(0.4,0.4) L12(0.4,1.2) L13(0.4,2) L14(0.4,2.8) L15(0.4,3.6) L16(0.4,4.4) L17(0.4,5.2) L18(0.4,6) L19(0.4,6.8) L20(0.4,7.6) M1(1.2,-7.6) M2(1.2,-6.8) M3(1.2,-6) M4(1.2,-5.2) M5(1.2,-4.4) M6(1.2,-3.6) M7(1.2,-2.8) M8(1.2,-2) M9(1.2,-1.2) M10(1.2,-0.4) M11(1.2,0.4) M12(1.2,1.2) M13(1.2,2) M14(1.2,2.8) M15(1.2,3.6) M16(1.2,4.4) M17(1.2,5.2) M18(1.2,6) M19(1.2,6.8) M20(1.2,7.6) N1(2,-7.6) N2(2,-6.8) N3(2,-6) N4(2,-5.2) N5(2,-4.4) N6(2,-3.6) N7(2,-2.8) N8(2,-2) N9(2,-1.2) N10(2,-0.4) N11(2,0.4) N12(2,1.2) N13(2,2) N14(2,2.8) N15(2,3.6) N16(2,4.4) N17(2,5.2) N18(2,6) N19(2,6.8) N20(2,7.6) P1(2.8,-7.6) P2(2.8,-6.8) P3(2.8,-6) P4(2.8,-5.2) P5(2.8,-4.4) P6(2.8,-3.6) P7(2.8,-2.8) P8(2.8,-2) P9(2.8,-1.2) P10(2.8,-0.4) P11(2.8,0.4) P12(2.8,1.2) P13(2.8,2) P14(2.8,2.8) P15(2.8,3.6) P16(2.8,4.4) P17(2.8,5.2) P18(2.8,6) P19(2.8,6.8) P20(2.8,7.6) R1(3.6,-7.6) R2(3.6,-6.8) R3(3.6,-6) R4(3.6,-5.2) R5(3.6,-4.4) R6(3.6,-3.6) R7(3.6,-2.8) R8(3.6,-2) R9(3.6,-1.2) R10(3.6,-0.4) R11(3.6,0.4) R12(3.6,1.2) R13(3.6,2) R14(3.6,2.8) R15(3.6,3.6) R16(3.6,4.4) R17(3.6,5.2) R18(3.6,6) R19(3.6,6.8) R20(3.6,7.6) T1(4.4,-7.6) T2(4.4,-6.8) T3(4.4,-6) T4(4.4,-5.2) T5(4.4,-4.4) T6(4.4,-3.6) T7(4.4,-2.8) T8(4.4,-2) T9(4.4,-1.2) T10(4.4,-0.4) T11(4.4,0.4) T12(4.4,1.2) T13(4.4,2) T14(4.4,2.8) T15(4.4,3.6) T16(4.4,4.4) T17(4.4,5.2) T18(4.4,6) T19(4.4,6.8) T20(4.4,7.6) U1(5.2,-7.6) U2(5.2,-6.8) U3(5.2,-6) U4(5.2,-5.2) U5(5.2,-4.4) U6(5.2,-3.6) U7(5.2,-2.8) U8(5.2,-2) U9(5.2,-1.2) U10(5.2,-0.4) U11(5.2,0.4) U12(5.2,1.2) U13(5.2,2) U14(5.2,2.8) U15(5.2,3.6) U16(5.2,4.4) U17(5.2,5.2) U18(5.2,6) U19(5.2,6.8) U20(5.2,7.6) V1(6,-7.6) V2(6,-6.8) V3(6,-6) V4(6,-5.2) V5(6,-4.4) V6(6,-3.6) V7(6,-2.8) V8(6,-2) V9(6,-1.2) V10(6,-0.4) V11(6,0.4) V12(6,1.2) V13(6,2) V14(6,2.8) V15(6,3.6) V16(6,4.4) V17(6,5.2) V18(6,6) V19(6,6.8) V20(6,7.6) W1(6.8,-7.6) W2(6.8,-6.8) W3(6.8,-6) W4(6.8,-5.2) W5(6.8,-4.4) W6(6.8,-3.6) W7(6.8,-2.8) W8(6.8,-2) W9(6.8,-1.2) W10(6.8,-0.4) W11(6.8,0.4) W12(6.8,1.2) W13(6.8,2) W14(6.8,2.8) W15(6.8,3.6) W16(6.8,4.4) W17(6.8,5.2) W18(6.8,6) W19(6.8,6.8) W20(6.8,7.6) Y1(7.6,-7.6) Y2(7.6,-6.8) Y3(7.6,-6) Y4(7.6,-5.2) Y5(7.6,-4.4) Y6(7.6,-3.6) Y7(7.6,-2.8) Y8(7.6,-2) Y9(7.6,-1.2) Y10(7.6,-0.4) Y11(7.6,0.4) Y12(7.6,1.2) Y13(7.6,2) Y14(7.6,2.8) Y15(7.6,3.6) Y16(7.6,4.4) Y17(7.6,5.2) Y18(7.6,6) Y19(7.6,6.8) Y20(7.6,7.6)
